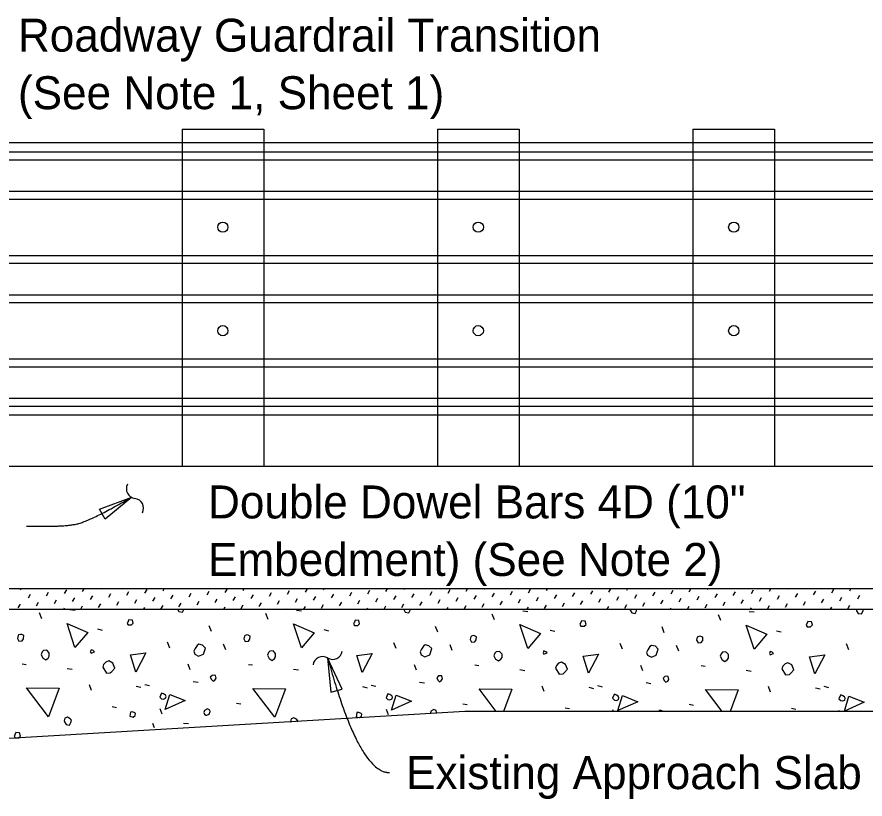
# Model space of a CAD drawing. Extents: x 21526.6 to 21598.7, y 56118.1 to 56155.9.
# Drawn here: x 21556.78 to 21561.97, y 56133.17 to 56137.96 of the extents above; entities that cross this region are included whole.
import ezdxf

# ---------------------------------------------------------------- set-up
doc = ezdxf.new("R2010")
doc.units = 0
for name, color, linetype in [('AdhocPoint_dp', 7, 'Continuous'), ('Border', 7, 'Continuous'), ('Patterning', 7, 'Continuous'), ('PlotBorder_dp', 7, 'Continuous'), ('SheetBorder_dp', 7, 'Continuous')]:
    doc.layers.add(name, color=color, linetype=linetype)

msp = doc.modelspace()

# ---------------------------------------------------------------- linework, layer by layer
at = {"layer": 'AdhocPoint_dp'}
for p, q in [((21554.3018, 56135.21), (21562.4118, 56135.21)), ((21565.8764, 56134.4601), (21554.3018, 56134.4601)), ((21554.3018, 56134.3351), (21565.8764, 56134.3351)), ((21559.5217, 56133.71), (21555.3017, 56133.4601)), ((21565.8764, 56133.71), (21559.5217, 56133.71))]:
    msp.add_line(p, q, dxfattribs=at)
at = {"layer": 'Patterning'}
for p, q in [((21557.7913, 56137.2725), (21557.7913, 56135.21)), ((21557.7913, 56137.2725), (21558.2913, 56137.2725)), ((21558.2913, 56137.2725), (21558.2913, 56135.21)), ((21559.3538, 56137.2725), (21559.3538, 56135.21)), ((21559.3538, 56137.2725), (21559.8538, 56137.2725)), ((21559.8538, 56137.2725), (21559.8538, 56135.21)), ((21560.9163, 56137.2725), (21560.9163, 56135.21)), ((21560.9163, 56137.2725), (21561.4163, 56137.2725)), ((21561.4163, 56137.2725), (21561.4163, 56135.21)), ((21556.803, 56134.4539), (21556.8066, 56134.4601)), ((21556.9624, 56134.418), (21556.9754, 56134.4404)), ((21557.0731, 56134.431), (21557.086, 56134.4534)), ((21557.1837, 56134.4439), (21557.1931, 56134.4601)), ((21557.2943, 56134.4569), (21557.2962, 56134.4601)), ((21557.4538, 56134.421), (21557.4668, 56134.4434)), ((21557.5644, 56134.434), (21557.5774, 56134.4564)), ((21557.6751, 56134.447), (21557.6827, 56134.4601)), ((21557.7857, 56134.4599), (21557.7858, 56134.4601)), ((21557.9452, 56134.424), (21557.9581, 56134.4464)), ((21558.0558, 56134.437), (21558.0688, 56134.4594)), ((21558.1664, 56134.45), (21558.1723, 56134.4601)), ((21558.3259, 56134.4141), (21558.3389, 56134.4365)), ((21558.4365, 56134.4271), (21558.4495, 56134.4495)), ((21558.5472, 56134.44), (21558.5588, 56134.4601)), ((21558.6578, 56134.453), (21558.6619, 56134.4601)), ((21558.8173, 56134.4171), (21558.8302, 56134.4395)), ((21558.9279, 56134.4301), (21558.9409, 56134.4525)), ((21559.0385, 56134.4431), (21559.0484, 56134.4601)), ((21559.1492, 56134.456), (21559.1515, 56134.4601)), ((21559.3086, 56134.4201), (21559.3216, 56134.4425)), ((21559.4193, 56134.4331), (21559.4322, 56134.4555)), ((21559.5299, 56134.4461), (21559.538, 56134.4601)), ((21559.6405, 56134.459), (21559.6412, 56134.4601)), ((21559.8, 56134.4232), (21559.813, 56134.4456)), ((21559.9106, 56134.4361), (21559.9236, 56134.4585)), ((21560.0213, 56134.4491), (21560.0276, 56134.4601)), ((21560.2914, 56134.4262), (21560.3043, 56134.4486)), ((21560.402, 56134.4391), (21560.4141, 56134.4601)), ((21560.5126, 56134.4521), (21560.5173, 56134.4601)), ((21560.6721, 56134.4162), (21560.6851, 56134.4386)), ((21560.7827, 56134.4292), (21560.7957, 56134.4516)), ((21560.8934, 56134.4422), (21560.9038, 56134.4601)), ((21561.004, 56134.4551), (21561.0069, 56134.4601)), ((21561.1635, 56134.4193), (21561.1764, 56134.4417)), ((21561.2741, 56134.4322), (21561.2871, 56134.4546)), ((21561.3847, 56134.4452), (21561.3934, 56134.4601)), ((21561.4954, 56134.4582), (21561.4965, 56134.4601)), ((21561.6548, 56134.4223), (21561.6678, 56134.4447)), ((21561.7655, 56134.4352), (21561.7784, 56134.4576)), ((21561.8761, 56134.4482), (21561.883, 56134.4601)), ((21556.8518, 56134.405), (21556.8648, 56134.4274)), ((21557.0113, 56134.3692), (21557.0242, 56134.3916)), ((21557.1219, 56134.3821), (21557.1349, 56134.4045)), ((21557.2325, 56134.3951), (21557.2455, 56134.4175)), ((21557.3432, 56134.4081), (21557.3561, 56134.4305)), ((21557.5026, 56134.3722), (21557.5156, 56134.3946)), ((21557.6133, 56134.3852), (21557.6262, 56134.4075)), ((21557.7239, 56134.3981), (21557.7369, 56134.4205)), ((21557.8345, 56134.4111), (21557.8475, 56134.4335)), ((21557.8834, 56134.3623), (21557.8963, 56134.3846)), ((21557.994, 56134.3752), (21558.007, 56134.3976)), ((21558.1046, 56134.3882), (21558.1176, 56134.4106)), ((21558.2153, 56134.4011), (21558.2282, 56134.4235)), ((21558.3747, 56134.3653), (21558.3877, 56134.3877)), ((21558.4854, 56134.3782), (21558.4983, 56134.4006)), ((21558.596, 56134.3912), (21558.609, 56134.4136)), ((21558.7066, 56134.4042), (21558.7196, 56134.4266)), ((21558.8661, 56134.3683), (21558.8791, 56134.3907)), ((21558.9767, 56134.3813), (21558.9897, 56134.4036)), ((21559.0874, 56134.3942), (21559.1003, 56134.4166)), ((21559.198, 56134.4072), (21559.211, 56134.4296)), ((21559.3575, 56134.3713), (21559.3704, 56134.3937)), ((21559.4681, 56134.3843), (21559.4811, 56134.4067)), ((21559.5787, 56134.3972), (21559.5917, 56134.4196)), ((21559.6894, 56134.4102), (21559.7023, 56134.4326)), ((21559.8488, 56134.3743), (21559.8618, 56134.3967)), ((21559.9595, 56134.3873), (21559.9724, 56134.4097)), ((21560.0701, 56134.4003), (21560.0831, 56134.4226)), ((21560.1807, 56134.4132), (21560.1937, 56134.4356)), ((21560.2296, 56134.3644), (21560.2425, 56134.3868)), ((21560.3402, 56134.3774), (21560.3532, 56134.3997)), ((21560.4508, 56134.3903), (21560.4638, 56134.4127)), ((21560.5615, 56134.4033), (21560.5744, 56134.4257)), ((21560.7209, 56134.3674), (21560.7339, 56134.3898)), ((21560.8316, 56134.3804), (21560.8445, 56134.4028)), ((21560.9422, 56134.3933), (21560.9552, 56134.4157)), ((21561.0528, 56134.4063), (21561.0658, 56134.4287)), ((21561.2123, 56134.3704), (21561.2253, 56134.3928)), ((21561.3229, 56134.3834), (21561.3359, 56134.4058)), ((21561.4336, 56134.3964), (21561.4465, 56134.4187)), ((21561.5442, 56134.4093), (21561.5572, 56134.4317)), ((21561.7037, 56134.3734), (21561.7166, 56134.3958)), ((21561.8143, 56134.3864), (21561.8273, 56134.4088)), ((21561.9249, 56134.3994), (21561.9379, 56134.4218)), ((21556.79, 56134.3432), (21556.803, 56134.3656)), ((21556.9006, 56134.3562), (21556.9136, 56134.3786)), ((21557.0686, 56134.3351), (21557.0731, 56134.3427)), ((21557.1061, 56134.3326), (21557.1379, 56134.3291)), ((21557.1718, 56134.3351), (21557.1837, 56134.3557)), ((21557.2814, 56134.3463), (21557.2943, 56134.3687)), ((21557.392, 56134.3592), (21557.405, 56134.3816)), ((21557.5582, 56134.3351), (21557.5644, 56134.3458)), ((21557.6621, 56134.3363), (21557.6751, 56134.3587)), ((21557.7727, 56134.3493), (21557.7857, 56134.3717)), ((21557.9447, 56134.3351), (21557.9452, 56134.3358)), ((21558.0479, 56134.3351), (21558.0558, 56134.3488)), ((21558.1535, 56134.3393), (21558.1664, 56134.3617)), ((21558.2641, 56134.3523), (21558.2771, 56134.3747)), ((21558.4343, 56134.3351), (21558.4365, 56134.3388)), ((21558.5375, 56134.3351), (21558.5472, 56134.3518)), ((21558.6448, 56134.3424), (21558.6578, 56134.3648)), ((21558.7555, 56134.3553), (21558.7684, 56134.3777)), ((21558.924, 56134.3351), (21558.9279, 56134.3418)), ((21559.0271, 56134.3351), (21559.0385, 56134.3548)), ((21559.1362, 56134.3454), (21559.1492, 56134.3678)), ((21559.2468, 56134.3583), (21559.2598, 56134.3807)), ((21559.4136, 56134.3351), (21559.4193, 56134.3449)), ((21559.5169, 56134.3354), (21559.5299, 56134.3578)), ((21559.6276, 56134.3484), (21559.6405, 56134.3708)), ((21559.7382, 56134.3614), (21559.7512, 56134.3838)), ((21559.9032, 56134.3351), (21559.9106, 56134.3479)), ((21560.0083, 56134.3385), (21560.0213, 56134.3609)), ((21560.1189, 56134.3514), (21560.1319, 56134.3738)), ((21560.2897, 56134.3351), (21560.2914, 56134.3379)), ((21560.3928, 56134.3351), (21560.402, 56134.3509)), ((21560.4997, 56134.3415), (21560.5126, 56134.3639)), ((21560.6103, 56134.3544), (21560.6233, 56134.3768)), ((21560.7793, 56134.3351), (21560.7827, 56134.341)), ((21560.8824, 56134.3351), (21560.8934, 56134.3539)), ((21560.991, 56134.3445), (21561.004, 56134.3669)), ((21561.1017, 56134.3575), (21561.1146, 56134.3799)), ((21561.2689, 56134.3351), (21561.2741, 56134.344)), ((21561.3721, 56134.3351), (21561.3847, 56134.3569)), ((21561.4824, 56134.3475), (21561.4954, 56134.3699)), ((21561.593, 56134.3605), (21561.606, 56134.3829)), ((21561.7585, 56134.3351), (21561.7655, 56134.347)), ((21561.8631, 56134.3376), (21561.8761, 56134.36)), ((21556.9334, 56134.2767), (21556.9193, 56134.312)), ((21558.3181, 56134.2732), (21558.304, 56134.3085)), ((21558.4907, 56134.3291), (21558.5225, 56134.3256)), ((21559.7028, 56134.2696), (21559.6886, 56134.305)), ((21559.8754, 56134.3256), (21559.9072, 56134.322)), ((21561.0875, 56134.2661), (21561.0733, 56134.3014)), ((21561.2601, 56134.322), (21561.2919, 56134.3185)), ((21557.9723, 56134.1983), (21557.9581, 56134.2336)), ((21559.3569, 56134.1947), (21559.3428, 56134.2301)), ((21557.274, 56134.2142), (21557.3023, 56134.2071)), ((21558.6587, 56134.2107), (21558.6869, 56134.2036)), ((21560.0433, 56134.2071), (21560.0716, 56134.2001)), ((21560.7416, 56134.1912), (21560.7275, 56134.2266)), ((21561.428, 56134.2036), (21561.4563, 56134.1965)), ((21557.7159, 56134.0975), (21557.7018, 56134.1329)), ((21559.1006, 56134.094), (21559.0865, 56134.1293)), ((21560.4853, 56134.0904), (21560.4711, 56134.1258)), ((21558.06, 56134.0858), (21558.0459, 56134.1211)), ((21559.4447, 56134.0822), (21559.4306, 56134.1176)), ((21560.8294, 56134.0787), (21560.8152, 56134.1141)), ((21561.87, 56134.0869), (21561.8558, 56134.1223)), ((21556.8132, 56134.0009), (21556.838, 56133.9974)), ((21557.089, 56133.9726), (21557.1191, 56133.9673)), ((21557.8414, 56133.9649), (21557.8291, 56133.9985)), ((21558.1979, 56133.9974), (21558.2227, 56133.9938)), ((21558.4737, 56133.9691), (21558.5037, 56133.9638)), ((21559.2261, 56133.9614), (21559.2137, 56133.995)), ((21559.5826, 56133.9938), (21559.6073, 56133.9903)), ((21560.6108, 56133.9579), (21560.5984, 56133.9915)), ((21560.9673, 56133.9903), (21560.992, 56133.9868)), ((21559.8584, 56133.9656), (21559.8884, 56133.9603)), ((21561.243, 56133.962), (21561.2731, 56133.9567)), ((21557.2375, 56133.8383), (21557.2251, 56133.8719)), ((21557.5639, 56133.8748), (21557.5922, 56133.8677)), ((21557.8603, 56133.8931), (21557.8903, 56133.8878)), ((21558.9486, 56133.8712), (21558.9769, 56133.8642)), ((21559.2449, 56133.8895), (21559.275, 56133.8842)), ((21560.3333, 56133.8677), (21560.3615, 56133.8606)), ((21560.6296, 56133.886), (21560.6597, 56133.8807)), ((21557.5115, 56133.8648), (21557.5398, 56133.8577)), ((21558.8962, 56133.8613), (21558.9245, 56133.8542)), ((21560.0068, 56133.8312), (21559.9945, 56133.8648)), ((21560.2808, 56133.8577), (21560.3091, 56133.8507)), ((21561.3915, 56133.8277), (21561.3791, 56133.8613)), ((21561.6655, 56133.8542), (21561.6938, 56133.8471)), ((21561.7179, 56133.8642), (21561.7462, 56133.8571)), ((21557.3648, 56133.7393), (21557.3913, 56133.734)), ((21557.67, 56133.6922), (21557.6576, 56133.7258)), ((21558.1237, 56133.7605), (21558.1502, 56133.7552)), ((21559.0546, 56133.6887), (21559.0423, 56133.7222)), ((21559.5083, 56133.757), (21559.5349, 56133.7517)), ((21560.1341, 56133.7322), (21560.1606, 56133.7269)), ((21560.4301, 56133.71), (21560.4269, 56133.7187)), ((21560.893, 56133.7534), (21560.9195, 56133.7481)), ((21561.5188, 56133.7287), (21561.5453, 56133.7234)), ((21561.8135, 56133.71), (21561.8116, 56133.7152)), ((21557.624, 56133.6092), (21557.6134, 56133.6358)), ((21557.8002, 56133.6385), (21557.832, 56133.635))]:
    msp.add_line(p, q, dxfattribs=at)
for points in [[(21557.7643, 56134.3351), (21557.7725, 56134.3203), (21557.7937, 56134.3167), (21557.8026, 56134.3326), (21557.8032, 56134.3351)], [(21559.1471, 56134.3351), (21559.1483, 56134.3326)], [(21559.1483, 56134.3326), (21559.1572, 56134.3167), (21559.1784, 56134.3132), (21559.1872, 56134.3291), (21559.1887, 56134.3351)], [(21560.53, 56134.3351), (21560.533, 56134.3291)], [(21560.533, 56134.3291), (21560.5419, 56134.3132), (21560.5631, 56134.3097), (21560.5719, 56134.3256), (21560.5743, 56134.3351)], [(21561.915, 56134.3351), (21561.9142, 56134.3326), (21561.9177, 56134.3256)], [(21561.9177, 56134.3256), (21561.9265, 56134.3097), (21561.9477, 56134.3061), (21561.9566, 56134.322), (21561.9598, 56134.3351)], [(21557.1367, 56134.1017), (21557.089, 56134.2484), (21557.2145, 56134.1936), (21557.1367, 56134.1017)], [(21557.4614, 56134.2389), (21557.4826, 56134.2389), (21557.4932, 56134.2495), (21557.4879, 56134.269), (21557.4649, 56134.2708), (21557.4614, 56134.2602), (21557.4561, 56134.2513), (21557.4614, 56134.2389), (21557.4578, 56134.2425)], [(21558.5214, 56134.0981), (21558.4737, 56134.2449), (21558.5992, 56134.1901), (21558.5214, 56134.0981)], [(21558.846, 56134.2354), (21558.8673, 56134.2354), (21558.8779, 56134.246), (21558.8726, 56134.2655), (21558.8496, 56134.2672), (21558.846, 56134.2566), (21558.8407, 56134.2478), (21558.846, 56134.2354), (21558.8425, 56134.2389)], [(21559.9061, 56134.0946), (21559.8584, 56134.2413), (21559.9839, 56134.1865), (21559.9061, 56134.0946)], [(21560.2307, 56134.2319), (21560.2519, 56134.2319), (21560.2625, 56134.2425), (21560.2572, 56134.2619), (21560.2343, 56134.2637), (21560.2307, 56134.2531), (21560.2254, 56134.2442), (21560.2307, 56134.2319), (21560.2272, 56134.2354)], [(21561.2908, 56134.0911), (21561.243, 56134.2378), (21561.3685, 56134.183), (21561.2908, 56134.0911)], [(21561.6154, 56134.2283), (21561.6366, 56134.2283), (21561.6472, 56134.2389), (21561.6419, 56134.2584), (21561.6189, 56134.2602), (21561.6154, 56134.2495), (21561.6101, 56134.2407), (21561.6154, 56134.2283), (21561.6119, 56134.2319)], [(21556.7849, 56134.1565), (21556.7938, 56134.1406), (21556.8132, 56134.1423), (21556.8221, 56134.1547), (21556.8238, 56134.1742), (21556.8115, 56134.1795), (21556.8026, 56134.1812), (21556.792, 56134.1777), (21556.7885, 56134.1742), (21556.7849, 56134.1565)], [(21558.1696, 56134.1529), (21558.1785, 56134.137), (21558.1979, 56134.1388), (21558.2067, 56134.1512), (21558.2085, 56134.1706), (21558.1961, 56134.1759), (21558.1873, 56134.1777), (21558.1767, 56134.1742), (21558.1732, 56134.1706), (21558.1696, 56134.1529)], [(21559.5543, 56134.1494), (21559.5631, 56134.1335), (21559.5826, 56134.1353), (21559.5914, 56134.1476), (21559.5932, 56134.1671), (21559.5808, 56134.1724), (21559.572, 56134.1742), (21559.5614, 56134.1706), (21559.5578, 56134.1671), (21559.5543, 56134.1494)], [(21560.939, 56134.1459), (21560.9478, 56134.13), (21560.9673, 56134.1317), (21560.9761, 56134.1441), (21560.9779, 56134.1636), (21560.9655, 56134.1689), (21560.9567, 56134.1706), (21560.946, 56134.1671), (21560.9425, 56134.1636), (21560.939, 56134.1459)], [(21556.9299, 56134.0575), (21556.9405, 56134.0363), (21556.9582, 56134.0257), (21556.9723, 56134.0363), (21556.9794, 56134.0469), (21556.9794, 56134.0681), (21556.9635, 56134.084), (21556.944, 56134.0822), (21556.9352, 56134.0734), (21556.9299, 56134.0575)], [(21557.2357, 56134.0663), (21557.2552, 56134.0752), (21557.2481, 56134.0822), (21557.2357, 56134.0875), (21557.2304, 56134.0752), (21557.2357, 56134.0663)], [(21557.8697, 56134.0604), (21557.8927, 56134.048), (21557.9228, 56134.0604), (21557.9351, 56134.0975), (21557.9175, 56134.1152), (21557.8945, 56134.1205), (21557.8839, 56134.1134), (21557.8715, 56134.094), (21557.8627, 56134.0781), (21557.8697, 56134.0604)], [(21558.3146, 56134.054), (21558.3252, 56134.0327), (21558.3429, 56134.0221), (21558.357, 56134.0327), (21558.3641, 56134.0433), (21558.3641, 56134.0646), (21558.3482, 56134.0805), (21558.3287, 56134.0787), (21558.3199, 56134.0699), (21558.3146, 56134.054)], [(21559.2544, 56134.0569), (21559.2774, 56134.0445), (21559.3074, 56134.0569), (21559.3198, 56134.094), (21559.3021, 56134.1117), (21559.2792, 56134.117), (21559.2685, 56134.1099), (21559.2562, 56134.0904), (21559.2473, 56134.0745), (21559.2544, 56134.0569)], [(21559.6993, 56134.0504), (21559.7099, 56134.0292), (21559.7275, 56134.0186), (21559.7417, 56134.0292), (21559.7488, 56134.0398), (21559.7488, 56134.061), (21559.7328, 56134.0769), (21559.7134, 56134.0752), (21559.7046, 56134.0663), (21559.6993, 56134.0504)], [(21560.0051, 56134.0593), (21560.0245, 56134.0681), (21560.0175, 56134.0752), (21560.0051, 56134.0805), (21559.9998, 56134.0681), (21560.0051, 56134.0593)], [(21560.6391, 56134.0533), (21560.6621, 56134.041), (21560.6921, 56134.0533), (21560.7045, 56134.0904), (21560.6868, 56134.1081), (21560.6638, 56134.1134), (21560.6532, 56134.1064), (21560.6408, 56134.0869), (21560.632, 56134.071), (21560.6391, 56134.0533)], [(21561.0839, 56134.0469), (21561.0945, 56134.0257), (21561.1122, 56134.0151), (21561.1264, 56134.0257), (21561.1334, 56134.0363), (21561.1334, 56134.0575), (21561.1175, 56134.0734), (21561.0981, 56134.0716), (21561.0892, 56134.0628), (21561.0839, 56134.0469)], [(21561.3898, 56134.0557), (21561.4092, 56134.0646), (21561.4021, 56134.0716), (21561.3898, 56134.0769), (21561.3845, 56134.0646), (21561.3898, 56134.0557)], [(21557.5091, 56133.9508), (21557.4755, 56134.0551), (21557.5692, 56134.0675), (21557.5091, 56133.9508)], [(21558.8938, 56133.9473), (21558.8602, 56134.0516), (21558.9539, 56134.0639), (21558.8938, 56133.9473)], [(21560.2785, 56133.9437), (21560.2449, 56134.048), (21560.3386, 56134.0604), (21560.2785, 56133.9437)], [(21561.6631, 56133.9402), (21561.6295, 56134.0445), (21561.7232, 56134.0569), (21561.6631, 56133.9402)], [(21557.3064, 56133.9815), (21557.3294, 56133.9444), (21557.3524, 56133.9461), (21557.3612, 56133.955), (21557.3807, 56133.9744), (21557.3683, 56134.0045), (21557.3436, 56134.0186), (21557.3259, 56134.0115), (21557.3117, 56133.9974), (21557.3064, 56133.9815)], [(21560.0758, 56133.9744), (21560.0988, 56133.9373), (21560.1218, 56133.939), (21560.1306, 56133.9479), (21560.15, 56133.9673), (21560.1377, 56133.9974), (21560.1129, 56134.0115), (21560.0952, 56134.0045), (21560.0811, 56133.9903), (21560.0758, 56133.9744)], [(21561.4605, 56133.9709), (21561.4834, 56133.9337), (21561.5064, 56133.9355), (21561.5153, 56133.9444), (21561.5347, 56133.9638), (21561.5223, 56133.9938), (21561.4976, 56134.008), (21561.4799, 56134.0009), (21561.4658, 56133.9868), (21561.4605, 56133.9709)], [(21557.9716, 56133.9055), (21557.9822, 56133.8949), (21557.9928, 56133.9019), (21557.9999, 56133.9125), (21557.9964, 56133.9302), (21557.9875, 56133.932), (21557.9752, 56133.9302), (21557.9646, 56133.9196), (21557.9716, 56133.9055)], [(21559.3563, 56133.9019), (21559.3669, 56133.8913), (21559.3775, 56133.8984), (21559.3846, 56133.909), (21559.3811, 56133.9267), (21559.3722, 56133.9284), (21559.3598, 56133.9267), (21559.3492, 56133.9161), (21559.3563, 56133.9019)], [(21560.741, 56133.8984), (21560.7516, 56133.8878), (21560.7622, 56133.8949), (21560.7693, 56133.9055), (21560.7657, 56133.9231), (21560.7569, 56133.9249), (21560.7445, 56133.9231), (21560.7339, 56133.9125), (21560.741, 56133.8984)], [(21556.9741, 56133.6774), (21556.8397, 56133.8542), (21557.0395, 56133.8524), (21556.9741, 56133.6774)], [(21557.6664, 56133.7864), (21557.6788, 56133.7846), (21557.6912, 56133.7899), (21557.6947, 56133.8005), (21557.6894, 56133.8094), (21557.6788, 56133.8164), (21557.6664, 56133.8217), (21557.6594, 56133.8076), (21557.6558, 56133.797), (21557.6664, 56133.7864)], [(21557.6888, 56133.7216), (21557.7171, 56133.8135), (21557.8108, 56133.7764), (21557.6888, 56133.7216)], [(21558.3588, 56133.6739), (21558.2244, 56133.8507), (21558.4242, 56133.8489), (21558.3588, 56133.6739)], [(21559.0511, 56133.7829), (21559.0635, 56133.7811), (21559.0759, 56133.7864), (21559.0794, 56133.797), (21559.0741, 56133.8058), (21559.0635, 56133.8129), (21559.0511, 56133.8182), (21559.044, 56133.8041), (21559.0405, 56133.7935), (21559.0511, 56133.7829)], [(21559.7133, 56133.71), (21559.6091, 56133.8471), (21559.8089, 56133.8454), (21559.7583, 56133.71)], [(21560.4358, 56133.7793), (21560.4482, 56133.7776), (21560.4605, 56133.7829), (21560.4641, 56133.7935), (21560.4588, 56133.8023), (21560.4482, 56133.8094), (21560.4358, 56133.8147), (21560.4287, 56133.8005), (21560.4252, 56133.7899), (21560.4358, 56133.7793)], [(21561.0953, 56133.71), (21560.9938, 56133.8436), (21561.1935, 56133.8418), (21561.1443, 56133.71)], [(21559.0735, 56133.7181), (21559.1017, 56133.81), (21559.1954, 56133.7729), (21559.0735, 56133.7181)], [(21560.4581, 56133.7145), (21560.4864, 56133.8065), (21560.5801, 56133.7693), (21560.4581, 56133.7145)], [(21561.8205, 56133.7758), (21561.8328, 56133.774), (21561.8452, 56133.7793), (21561.8487, 56133.7899), (21561.8434, 56133.7988), (21561.8328, 56133.8058), (21561.8205, 56133.8111), (21561.8134, 56133.797), (21561.8099, 56133.7864), (21561.8205, 56133.7758)], [(21561.8428, 56133.711), (21561.8711, 56133.8029), (21561.9648, 56133.7658), (21561.8428, 56133.711)], [(21557.9363, 56133.6863), (21557.9433, 56133.6863), (21557.9575, 56133.6933), (21557.9628, 56133.7092), (21557.961, 56133.7181), (21557.9469, 56133.7251), (21557.9292, 56133.7145), (21557.9257, 56133.7039), (21557.9292, 56133.6933), (21557.9363, 56133.6863)], [(21559.3452, 56133.699), (21559.3475, 56133.7057), (21559.3457, 56133.7145), (21559.3316, 56133.7216), (21559.3139, 56133.711), (21559.3103, 56133.7004), (21559.3115, 56133.6969)], [(21560.7306, 56133.71), (21560.7304, 56133.711), (21560.7162, 56133.7181), (21560.7028, 56133.71)], [(21557.0731, 56133.6456), (21557.0819, 56133.6297), (21557.1031, 56133.6262), (21557.112, 56133.6421), (21557.1155, 56133.6562), (21557.1067, 56133.665), (21557.0908, 56133.6739), (21557.0749, 56133.6686), (21557.0696, 56133.6527), (21557.0731, 56133.6456)], [(21557.4726, 56133.681), (21557.492, 56133.6756), (21557.5044, 56133.6845), (21557.5062, 56133.6969), (21557.5027, 56133.7004), (21557.4885, 56133.7075), (21557.4761, 56133.7057), (21557.4744, 56133.6933), (21557.4726, 56133.681)], [(21558.4985, 56133.6461), (21558.5002, 56133.6527), (21558.4914, 56133.6615), (21558.4754, 56133.6703), (21558.4595, 56133.665), (21558.4542, 56133.6491), (21558.4571, 56133.6435)], [(21558.8573, 56133.6774), (21558.8767, 56133.6721), (21558.8891, 56133.681), (21558.8909, 56133.6933), (21558.8873, 56133.6969), (21558.8732, 56133.7039), (21558.8608, 56133.7022), (21558.859, 56133.6898), (21558.8573, 56133.6774)], [(21556.7708, 56133.5484), (21556.792, 56133.5484), (21556.8026, 56133.559), (21556.7973, 56133.5784), (21556.7743, 56133.5802), (21556.7708, 56133.5696), (21556.7655, 56133.5607), (21556.7708, 56133.5484), (21556.7673, 56133.5519)]]:
    msp.add_lwpolyline(points, dxfattribs=at)
at = {"layer": 'PlotBorder_dp'}
for points in [[(21557.4838, 56135.0207), (21557.3212, 56134.8859), (21557.2858, 56134.947)], [(21558.6823, 56134.0371), (21558.7024, 56133.8269), (21558.7706, 56133.8452)]]:
    msp.add_lwpolyline(points, close=True, dxfattribs=at)
for centre, start, end in [((21557.5105, 56135.0721), 151.5267, 263.2539), ((21557.4965, 56134.9537), 331.5267, 83.2539), ((21558.7125, 56134.0879), 239.2651, 350.9923), ((21558.6515, 56133.9854), 59.2651, 170.9923)]:
    msp.add_arc(centre, 0.0596, start, end, dxfattribs=at)
for points in [[(21556.8393, 56134.8438), (21557.056, 56134.8381), (21557.2271, 56134.8723), (21557.4838, 56135.0207)], [(21558.6827, 56134.0369), (21558.8719, 56133.3352), (21559.061, 56133.3352)]]:
    msp.add_open_spline(points, degree=2, dxfattribs=at)
at = {"layer": 'SheetBorder_dp'}
for p, q in [((21564.1633, 56137.1891), (21552.8484, 56137.1891)), ((21552.8484, 56137.1336), (21564.1633, 56137.1336)), ((21552.8484, 56137.0853), (21564.1633, 56137.0853)), ((21552.8484, 56136.8925), (21564.1633, 56136.8925)), ((21552.8484, 56136.8443), (21564.1633, 56136.8443)), ((21552.8484, 56136.5003), (21564.1633, 56136.5003)), ((21552.8484, 56136.4521), (21564.1633, 56136.4521)), ((21552.8484, 56136.2593), (21564.1633, 56136.2593)), ((21552.8484, 56136.2112), (21564.1633, 56136.2112)), ((21552.8484, 56135.8672), (21564.1633, 56135.8672)), ((21552.8484, 56135.819), (21564.1633, 56135.819)), ((21552.8484, 56135.6262), (21564.1633, 56135.6262)), ((21552.8484, 56135.5779), (21564.1633, 56135.5779)), ((21564.1633, 56135.5224), (21552.8484, 56135.5224))]:
    msp.add_line(p, q, dxfattribs=at)
for centre in [(21558.0413, 56136.6724), (21559.6038, 56136.6724), (21561.1663, 56136.6724), (21558.0413, 56136.0393), (21559.6038, 56136.0393), (21561.1663, 56136.0393)]:
    msp.add_circle(centre, 0.0312, dxfattribs=at)

# ---------------------------------------------------------------- texts
at = {"layer": 'Border'}
msp.add_text('Existing Approach Slab', height=0.2016, dxfattribs=at).set_placement((21559.1619, 56133.2344))
at = {"layer": 'PlotBorder_dp'}
for s, p in [('Roadway Guardrail Transition', (21556.788, 56137.7466)), ('(See Note 1, Sheet 1)', (21556.788, 56137.3946)), ('Double Dowel Bars 4D (10" ', (21557.9507, 56134.8907)), ('Embedment) (See Note 2)', (21557.9507, 56134.5387))]:
    msp.add_text(s, height=0.2016, dxfattribs=at).set_placement(p)

doc.saveas('drawing.dxf')
